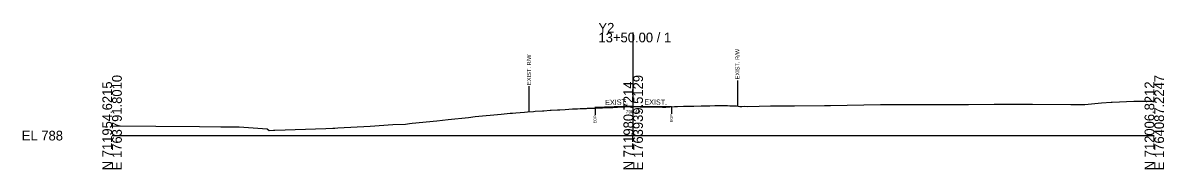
# Model space of a CAD drawing. Extents: x -26 to 1764011, y -10 to 712381.
# Drawn here: x -25.7 to 302.8, y 3490.3 to 3532.5 of the extents above; entities that cross this region are included whole.
import ezdxf

# ---------------------------------------------------------------- set-up
doc = ezdxf.new("R2010")
doc.units = 0
for name, color, linetype in [('Exist Cross Section Cell', 7, 'Continuous'), ('Exist XS Center Line Elevation Label', 7, 'Continuous'), ('Exist XS Ground Line', 7, 'Continuous'), ('Old_Level_10', 7, 'Continuous'), ('Prop CMT Pvmt Surface Overlay', 7, 'Continuous'), ('Prop XS SE Text', 7, 'Continuous')]:
    doc.layers.add(name, color=color, linetype=linetype)

msp = doc.modelspace()

# ---------------------------------------------------------------- linework, layer by layer
at = {"layer": 'Exist Cross Section Cell'}
for p, q in [((150, 3500), (150, 3529.69)), ((0, 3500), (150, 3500)), ((150, 3500), (300, 3500))]:
    msp.add_line(p, q, dxfattribs=at)
at = {"layer": 'Exist XS Ground Line'}
msp.add_lwpolyline([(0, 3502.79), (25.2, 3502.61), (31.31, 3502.57), (35.83, 3502.57), (36.58, 3502.53), (44.63, 3501.97), (45.19, 3501.47), (46.42, 3501.53), (46.88, 3501.56), (61.48, 3502.08), (63.54, 3502.16), (64.14, 3502.18), (65, 3502.23), (74.3, 3502.72), (80.8, 3503.19), (84.47, 3503.32), (85.01, 3503.41), (85.6, 3503.47), (86.41, 3503.56), (93.43, 3504.25), (95.1, 3504.42), (96.75, 3504.6), (102.57, 3505.24), (104.53, 3505.51), (111.97, 3506.21), (114.55, 3506.42), (115.28, 3506.48), (116.22, 3506.58), (117.44, 3506.69), (118.76, 3506.79), (119.59, 3506.87), (121.3, 3506.98), (121.75, 3507), (123.91, 3507.16), (124.3, 3507.18), (126.07, 3507.29), (126.38, 3507.31), (128.22, 3507.42), (128.92, 3507.45), (130.38, 3507.56), (131.45, 3507.63), (132.54, 3507.69), (133.99, 3507.76), (134.7, 3507.78), (136.53, 3507.86), (136.85, 3507.87), (138.67, 3507.94), (139.07, 3507.95), (141.17, 3508.05), (141.61, 3508.06), (143.33, 3508.13), (144.15, 3508.15), (145.48, 3508.2), (146.69, 3508.27), (147.64, 3508.32), (149.44, 3508.39), (150.05, 3508.41), (150.96, 3508.38), (151.96, 3508.34), (153.04, 3508.33), (154.3, 3508.32), (156.27, 3508.28), (156.84, 3508.27), (158.43, 3508.24), (159.38, 3508.2), (160.59, 3508.27), (161.92, 3508.38), (162.74, 3508.41), (164.46, 3508.46), (164.9, 3508.46), (167.06, 3508.51), (167.41, 3508.52), (169.54, 3508.56), (171.37, 3508.6), (172.07, 3508.62), (173.53, 3508.66), (174.61, 3508.66), (175.69, 3508.66), (177.15, 3508.64), (177.85, 3508.61), (179.69, 3508.56), (180.74, 3508.35), (181.23, 3508.35), (182.08, 3508.48), (182.97, 3508.39), (189.52, 3508.54), (193.98, 3508.6), (195.5, 3508.63), (196.14, 3508.63), (196.47, 3508.63), (205.03, 3508.67), (206.84, 3508.7), (221.19, 3508.98), (221.83, 3508.98), (222.41, 3509), (223.65, 3509.01), (240.2, 3508.94), (242.82, 3508.95), (246.5, 3508.99), (253.9, 3509.11), (258.55, 3509.04), (263.27, 3509.04), (264.97, 3509.04), (276.01, 3508.97), (279.96, 3508.99), (284.84, 3509.4), (287.58, 3509.65), (287.91, 3509.65), (294.12, 3509.9), (300, 3509.89)], dxfattribs=at)
at = {"layer": 'Old_Level_10'}
for p, q in [((180, 3515.9), (180, 3508.5)), ((120, 3514.3), (120, 3506.9)), ((139.01, 3507.95), (139.01, 3505.9)), ((161, 3508.3), (161, 3506.25))]:
    msp.add_line(p, q, dxfattribs=at)
at = {"layer": 'Prop CMT Pvmt Surface Overlay'}
for p, q in [((150, 3508.53), (139, 3508.07)), ((150, 3508.4), (139.01, 3507.95)), ((150, 3508.53), (161, 3508.43)), ((150, 3508.4), (161, 3508.3))]:
    msp.add_line(p, q, dxfattribs=at)

# ---------------------------------------------------------------- texts
at = {"layer": 'Exist Cross Section Cell'}
for s, p in [('Y2', (140, 3529.69)), ('13+50.00 / 1', (140, 3526.89)), ('EL 788', (-26, 3498.6))]:
    msp.add_text(s, height=2.8, dxfattribs=at).set_placement(p)
for s, p in [('N 711954.6215', (0, 3490)), ('E 1763791.8010', (2.8, 3490)), ('N 711980.7214', (150, 3490)), ('E 1763939.5129', (152.8, 3490)), ('N 712006.8212', (300, 3490)), ('E 1764087.2247', (302.8, 3490))]:
    msp.add_text(s, height=2.8, rotation=90, dxfattribs=at).set_placement(p)
at = {"layer": 'Exist XS Center Line Elevation Label'}
msp.add_text('796.40', height=1, dxfattribs=at).set_placement((147.85, 3506.4))
at = {"layer": 'Old_Level_10'}
for s, height, p in [('EXIST. R/W', 1.181, (120.59, 3514.6)), ('EXIST. R/W', 1.181, (180.59, 3516.2)), ('EOP', 0.787, (139.4, 3503.5)), ('EOP', 0.787, (161.39, 3503.85))]:
    msp.add_text(s, height=height, rotation=90, dxfattribs=at).set_placement(p)
at = {"layer": 'Prop XS SE Text'}
for rotation, p in [(1.6611, (141.95, 3508.78)), (358.9688, (153.2, 3508.97))]:
    msp.add_text('EXIST.', height=1.5, rotation=rotation, dxfattribs=at).set_placement(p)

doc.saveas('drawing.dxf')
